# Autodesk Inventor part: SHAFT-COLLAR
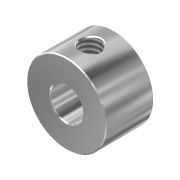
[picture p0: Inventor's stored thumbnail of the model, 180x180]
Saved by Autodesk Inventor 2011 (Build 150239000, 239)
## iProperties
Created: 2008-03
Part Number: SHAFT-COLLAR
Document SubType Name: Modeling
Density: 1 g/cm^3
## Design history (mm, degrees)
sketch "Sketch1"
  geometry: C1 r 5.499 at (-7.091, -3.091)
  constraints: 1 centre point
  dimensions: "d0" = 10.9982 diameter of C1
extrude "Extrusion1" new body sketch "Sketch1" distance "d1" = 6.604; taper "d2" = 0 deg
sketch "Sketch2"
  geometry: C1 r 5.499 at (0, 0) reference
hole "Hole1" sketch "Sketch2" at (0, 0) diameter "d3" = 4.4704; stored, may be unused: countersink angle "d7" = 82 deg, drill point angle "d9" = 118 deg; dims "d4" = 12.7, "d5" = 9.525, "d6" = 6.35, "d8" = 19.05
workplane "Work Plane1"
sketch "Sketch3"
  geometry: L1 (-5.499, 0)-(5.499, 0) reference; L2 (-5.499, 0)-(-5.499, -6.604) reference; 3 further points
  constraints: 2 midpoint, 1 horizontal alignment, 1 vertical alignment
hole "Hole2" sketch "Sketch3" at (0, -3.302) diameter "d10" = 2.8194; stored, may be unused: countersink angle "d14" = 82 deg, drill point angle "d16" = 118 deg; dims "d11" = 12.7, "d12" = 9.525, "d13" = 6.35, "d15" = 19.05
chamfer "Chamfer1" distance "d17" = 0.127; stored, may be unused: second distance "d18" = 3.175, angle "d19" = 45 deg
chamfer "Chamfer2" distance "d20" = 0.127; stored, may be unused: second distance "d21" = 3.175, angle "d22" = 45 deg
chamfer "Chamfer3" distance "d24" = 0.127; stored, may be unused: second distance "d25" = 3.175, angle "d26" = 45 deg
body "Solid1"
node "Projected Loop1"
